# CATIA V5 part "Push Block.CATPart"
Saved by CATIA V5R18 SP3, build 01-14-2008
Part number: Turn Table Guide Base
Bounding box of the stored display mesh (mm): x -12.5 to 12.5, y -37.5 to 37.5, z -37.491 to 37.491
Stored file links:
  E:\#00 CATIA V5 Movie\#03 CATIA V5 Data\#07 KIN\Balance Unit (1)\Push Block.CATPart
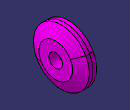
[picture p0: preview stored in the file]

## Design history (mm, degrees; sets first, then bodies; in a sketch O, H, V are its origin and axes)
Body1 "PartBody" (main body)
  Solid1: solid without history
